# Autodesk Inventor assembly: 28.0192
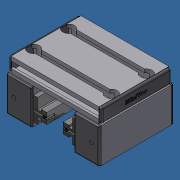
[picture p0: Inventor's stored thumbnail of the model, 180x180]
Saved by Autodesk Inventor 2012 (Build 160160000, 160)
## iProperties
Created: 2007-06
Part Number: 28.0192
Document SubType Name: Assembly
Designer: Andy Moles
Description: SLIDE LWN 32X45-45
Author: Andy Moles
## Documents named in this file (8)
- C:\Andys Backup Data\ANDY'S INVENTOR\INVENTOR LIBRARIES\PARTS LIBRARY\READY FOR USE MODULES LG\28.0192 SLIDE LWN 32X45-45.iam
- C:\Andys Backup Data\ANDY'S INVENTOR\INVENTOR LIBRARIES\PARTS LIBRARY\READY FOR USE MODULES LG\SUBCOMPONENTS\28.0222 SLIDE LWN 32X45-45 90X19.ipt
- C:\Andys Backup Data\ANDY'S INVENTOR\INVENTOR LIBRARIES\PARTS LIBRARY\READY FOR USE MODULES LG\SUBCOMPONENTS\28.0126 SLIDE 45X32.ipt
- C:\Andys Backup Data\ANDY'S INVENTOR\INVENTOR LIBRARIES\PARTS LIBRARY\COMPONENTS LG\22.1095 SLIDE RAIL LN.iam
- C:\Andys Backup Data\ANDY'S INVENTOR\INVENTOR LIBRARIES\PARTS LIBRARY\FASTENING ELEMENTS\SCREWS CAP\21.1200 M8X16.ipt
- C:\Andys Backup Data\ANDY'S INVENTOR\INVENTOR LIBRARIES\PARTS LIBRARY\FASTENING ELEMENTS\NUTS\21.1351 M8 SQUARE NUT.ipt
- C:\Andys Backup Data\ANDY'S INVENTOR\INVENTOR LIBRARIES\PARTS LIBRARY\END CAPS\22.1014_1 END CAP 90X19 GRAY.ipt
- C:\Andys Backup Data\ANDY'S INVENTOR\INVENTOR LIBRARIES\PARTS LIBRARY\END CAPS\22.1003_1 END CAP 45x32 Z Gray.iam
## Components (19 placed, 7 different names)
1. 28.0222 SLIDE LWN 32X45-45 90X19:1 — Mate:1, Mate:2, Flush:1, Mate:3, Flush:2, Flush:3, Mate:4, Flush:4, Flush:5, Flush:18, Flush:19, Insert:1, Insert:2, Insert:3, Insert:4, Insert:5, Insert:6, Insert:7, Insert:8, Mate:15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
2. 28.0126 SLIDE 45X32:1 — Mate:3, Flush:2, Flush:3, Mate:11, Mate:12, Mate:18, Flush:26, Flush:27, Mate:19, Flush:28, Flush:29
3. 28.0126 SLIDE 45X32:2 — Mate:4, Flush:4, Flush:5, Mate:13, Mate:14, Mate:17, Flush:24, Flush:25, Mate:20, Flush:30, Flush:31
4. 22.1014_1 END CAP 90X19 GRAY:1 — Mate:16, Flush:22, Flush:23
5. 22.1014_1 END CAP 90X19 GRAY:2 — Mate:15, Flush:20, Flush:21
6. 22.1095 SLIDE RAIL LN:1 [sub-assembly] — Mate:11, Flush:18, Mate:12
7. 22.1095 SLIDE RAIL LN:3 [sub-assembly] — Mate:13, Flush:19, Mate:14
8. 21.1200 M8 x 16:1 — Insert:1
9. 21.1200 M8 x 16:2 — Insert:2
10. 21.1200 M8 x 16:3 — Insert:3
11. 21.1200 M8 x 16:4 — Insert:4
12. 21.1351 M8 SQUARE NUT:1 — Insert:5
13. 21.1351 M8 SQUARE NUT:2 — Insert:6
14. 21.1351 M8 SQUARE NUT:3 — Insert:8
15. 21.1351 M8 SQUARE NUT:4 — Insert:7
16. 22.1003_1 END CAP 45x32 Z Gray:1 [sub-assembly] — Mate:17, Flush:24, Flush:25
17. 22.1003_1 END CAP 45x32 Z Gray:2 [sub-assembly] — Mate:18, Flush:26, Flush:27
18. 22.1003_1 END CAP 45x32 Z Gray:3 [sub-assembly] — Mate:20, Flush:30, Flush:31
19. 22.1003_1 END CAP 45x32 Z Gray:4 [sub-assembly] — Mate:19, Flush:28, Flush:29
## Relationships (41: Flush 19, Mate 14, Insert 8)
- Mate:1: 28.0222 SLIDE LWN 32X45-45 90X19:1
- Mate:2: 28.0222 SLIDE LWN 32X45-45 90X19:1
- Flush:1: 28.0222 SLIDE LWN 32X45-45 90X19:1
- Mate:3: 28.0222 SLIDE LWN 32X45-45 90X19:1 ↔ 28.0126 SLIDE 45X32:1
- Flush:2: 28.0222 SLIDE LWN 32X45-45 90X19:1 ↔ 28.0126 SLIDE 45X32:1
- Flush:3: 28.0222 SLIDE LWN 32X45-45 90X19:1 ↔ 28.0126 SLIDE 45X32:1
- Mate:4: 28.0222 SLIDE LWN 32X45-45 90X19:1 ↔ 28.0126 SLIDE 45X32:2
- Flush:4: 28.0222 SLIDE LWN 32X45-45 90X19:1 ↔ 28.0126 SLIDE 45X32:2
- Flush:5: 28.0222 SLIDE LWN 32X45-45 90X19:1 ↔ 28.0126 SLIDE 45X32:2
- Mate:11: 28.0126 SLIDE 45X32:1 ↔ 22.1095 SLIDE RAIL LN:1
- Flush:18: 28.0222 SLIDE LWN 32X45-45 90X19:1 ↔ 22.1095 SLIDE RAIL LN:1
- Mate:12: 28.0126 SLIDE 45X32:1 ↔ 22.1095 SLIDE RAIL LN:1
- Mate:13: 28.0126 SLIDE 45X32:2 ↔ 22.1095 SLIDE RAIL LN:3
- Flush:19: 28.0222 SLIDE LWN 32X45-45 90X19:1 ↔ 22.1095 SLIDE RAIL LN:3
- Mate:14: 28.0126 SLIDE 45X32:2 ↔ 22.1095 SLIDE RAIL LN:3
- Insert:1: 28.0222 SLIDE LWN 32X45-45 90X19:1 ↔ 21.1200 M8 x 16:1
- Insert:2: 28.0222 SLIDE LWN 32X45-45 90X19:1 ↔ 21.1200 M8 x 16:2
- Insert:3: 28.0222 SLIDE LWN 32X45-45 90X19:1 ↔ 21.1200 M8 x 16:3
- Insert:4: 28.0222 SLIDE LWN 32X45-45 90X19:1 ↔ 21.1200 M8 x 16:4
- Insert:5: 28.0222 SLIDE LWN 32X45-45 90X19:1 ↔ 21.1351 M8 SQUARE NUT:1
- Insert:6: 28.0222 SLIDE LWN 32X45-45 90X19:1 ↔ 21.1351 M8 SQUARE NUT:2
- Insert:7: 28.0222 SLIDE LWN 32X45-45 90X19:1 ↔ 21.1351 M8 SQUARE NUT:4
- Insert:8: 28.0222 SLIDE LWN 32X45-45 90X19:1 ↔ 21.1351 M8 SQUARE NUT:3
- Mate:15: 28.0222 SLIDE LWN 32X45-45 90X19:1 ↔ 22.1014_1 END CAP 90X19 GRAY:2
- Flush:20: 28.0222 SLIDE LWN 32X45-45 90X19:1 ↔ 22.1014_1 END CAP 90X19 GRAY:2
- Flush:21: 28.0222 SLIDE LWN 32X45-45 90X19:1 ↔ 22.1014_1 END CAP 90X19 GRAY:2
- Mate:16: 28.0222 SLIDE LWN 32X45-45 90X19:1 ↔ 22.1014_1 END CAP 90X19 GRAY:1
- Flush:22: 28.0222 SLIDE LWN 32X45-45 90X19:1 ↔ 22.1014_1 END CAP 90X19 GRAY:1
- Flush:23: 28.0222 SLIDE LWN 32X45-45 90X19:1 ↔ 22.1014_1 END CAP 90X19 GRAY:1
- Mate:17: 28.0126 SLIDE 45X32:2 ↔ 22.1003_1 END CAP 45x32 Z Gray:1
- Flush:24: 28.0126 SLIDE 45X32:2 ↔ 22.1003_1 END CAP 45x32 Z Gray:1
- Flush:25: 28.0126 SLIDE 45X32:2 ↔ 22.1003_1 END CAP 45x32 Z Gray:1
- Mate:18: 28.0126 SLIDE 45X32:1 ↔ 22.1003_1 END CAP 45x32 Z Gray:2
- Flush:26: 28.0126 SLIDE 45X32:1 ↔ 22.1003_1 END CAP 45x32 Z Gray:2
- Flush:27: 28.0126 SLIDE 45X32:1 ↔ 22.1003_1 END CAP 45x32 Z Gray:2
- Mate:19: 28.0126 SLIDE 45X32:1 ↔ 22.1003_1 END CAP 45x32 Z Gray:4
- Flush:28: 28.0126 SLIDE 45X32:1 ↔ 22.1003_1 END CAP 45x32 Z Gray:4
- Flush:29: 28.0126 SLIDE 45X32:1 ↔ 22.1003_1 END CAP 45x32 Z Gray:4
- Mate:20: 28.0126 SLIDE 45X32:2 ↔ 22.1003_1 END CAP 45x32 Z Gray:3
- Flush:30: 28.0126 SLIDE 45X32:2 ↔ 22.1003_1 END CAP 45x32 Z Gray:3
- Flush:31: 28.0126 SLIDE 45X32:2 ↔ 22.1003_1 END CAP 45x32 Z Gray:3
